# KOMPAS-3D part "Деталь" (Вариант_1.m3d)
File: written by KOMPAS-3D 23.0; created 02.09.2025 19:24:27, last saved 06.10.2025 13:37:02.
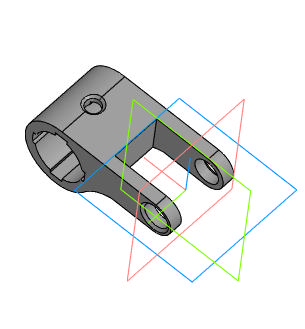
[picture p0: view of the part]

Document properties: Автор: ssafo; Полное имя файла: Вариант_1_Чертеж.cdw

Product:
- Part/product: Деталь
    Масса: 0.115521
    Форматы листов документа: A4

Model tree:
1. Эскиз:1
2. Элемент выдавливания:1
     Расстояние 1 = 15; Расстояние 2 = 15
3. Эскиз:2  (with: Элемент выдавливания:1)
4. Элемент выдавливания:2
     Расстояние 2 = 30
5. Эскиз:4  (with: Элемент выдавливания:1, Элемент выдавливания:2)
6. Элемент выдавливания:4
     Расстояние 2 = 15
7. Фаска:2  (with: Элемент выдавливания:2)
     Угол = 45; Длина 1 = 1; Длина 2 = 1
8. Зеркальный массив:1
9. Экземпляр ( 1 )
10. Экземпляр ( 2 )  (with: Элемент выдавливания:2, Элемент выдавливания:4, Фаска:2)
11. Эскиз:7  (with: Элемент выдавливания:1)
12. Элемент выдавливания:7
     Расстояние 1 = 10; Расстояние 2 = 10
13. Эскиз:8  (with: Элемент выдавливания:1)
14. Эскиз:9  (with: Элемент выдавливания:1)
15. Элемент выдавливания:9
     Расстояние 1 = 10; Расстояние 2 = 27.9996
16. Фаска:3  (with: Элемент выдавливания:9)
     Угол = 45; Длина 1 = 1; Длина 2 = 1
